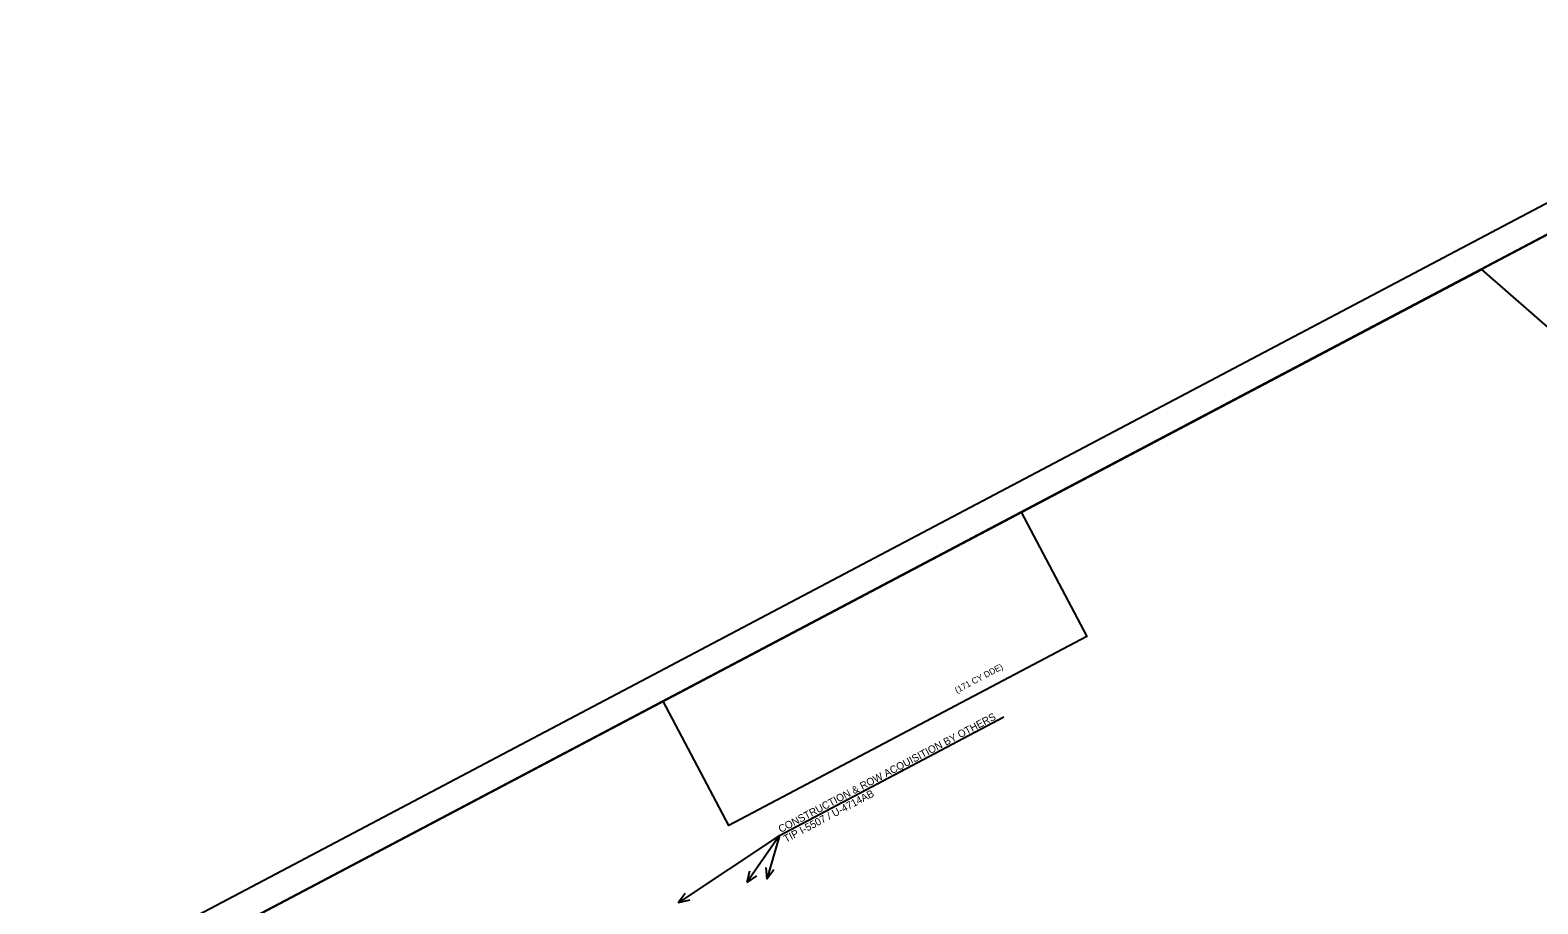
# Model space of a CAD drawing. Extents: x 1486990 to 1489232, y 497582 to 499336.
# Drawn here: x 1487051 to 1488268, y 498631 to 499336 of the extents above; entities that cross this region are included whole.
import ezdxf

# ---------------------------------------------------------------- set-up
doc = ezdxf.new("R2010")
doc.units = 0
for name, color, linetype in [('Default', 7, 'Continuous'), ('Prop Drainage Ditch Boundaries', 7, 'Continuous'), ('Prop Drainage Structure Catch Basin Open Throat 1 CELL', 7, 'Continuous'), ('Prop Drainage Structure Pipe Outlet Channel Detail CELL', 7, 'Continuous'), ('Prop Drainage Structure Plot Symbol 20 Scale', 7, 'Continuous')]:
    doc.layers.add(name, color=color, linetype=linetype)

msp = doc.modelspace()

# ---------------------------------------------------------------- linework, layer by layer
at = {"layer": 'Prop Drainage Ditch Boundaries'}
msp.add_lwpolyline([(1487562.2, 497582), (1489050.9, 498368), (1488539.7, 499336.3), (1487050.9, 498550.3)], close=True, dxfattribs=at)
at = {"layer": 'Prop Drainage Structure Catch Basin Open Throat 1 CELL'}
for points in [[(1488535.1, 499308.5), (1487208.7, 498608.1), (1487698.9, 497679.6), (1489025.4, 498380)], [(1487698.9, 497679.6), (1487208.7, 498608.1), (1488358.2, 499215.1), (1488428.3, 499082.4), (1488605.2, 499175.8), (1489025.4, 498380)], [(1487561.9, 498794.6), (1487850.8, 498947.1), (1487903.8, 498846.8), (1487614.9, 498694.3)]]:
    msp.add_lwpolyline(points, close=True, dxfattribs=at)
at = {"layer": 'Prop Drainage Structure Pipe Outlet Channel Detail CELL'}
for p, q in [((1487655.6, 498686.3), (1487836.8, 498782)), ((1487655.6, 498686.3), (1487573.9, 498631.8)), ((1487655.6, 498686.3), (1487629.2, 498648.2)), ((1487655.6, 498686.3), (1487645.4, 498650.9)), ((1487631.6, 498657.4), (1487629.2, 498648.2)), ((1487637, 498653.7), (1487629.2, 498648.2)), ((1487644.7, 498660.4), (1487645.4, 498650.9)), ((1487651, 498658.6), (1487645.4, 498650.9)), ((1487579.6, 498639.5), (1487573.9, 498631.8)), ((1487583.2, 498634), (1487573.9, 498631.8))]:
    msp.add_line(p, q, dxfattribs=at)
at = {"layer": 'Prop Drainage Structure Plot Symbol 20 Scale'}
msp.add_lwpolyline([(1487208.7, 498608.1), (1488222.1, 499143.2), (1488965.4, 498493.7), (1489025.4, 498380), (1487699, 497679.6)], close=True, dxfattribs=at)

# ---------------------------------------------------------------- texts
at = {"layer": 'Default'}
msp.add_text('(171 CY DDE)', height=5, rotation=27.8351, dxfattribs=at).set_placement((1487798.8, 498800.9))
at = {"layer": 'Prop Drainage Structure Pipe Outlet Channel Detail CELL'}
for s, p in [('CONSTRUCTION & ROW ACQUISITION BY OTHERS', (1487656.7, 498688.2)), ('TIP I-5507 / U-4714AB', (1487660.9, 498680.3))]:
    msp.add_text(s, height=6, rotation=27.8351, dxfattribs=at).set_placement(p)

doc.saveas('drawing.dxf')
